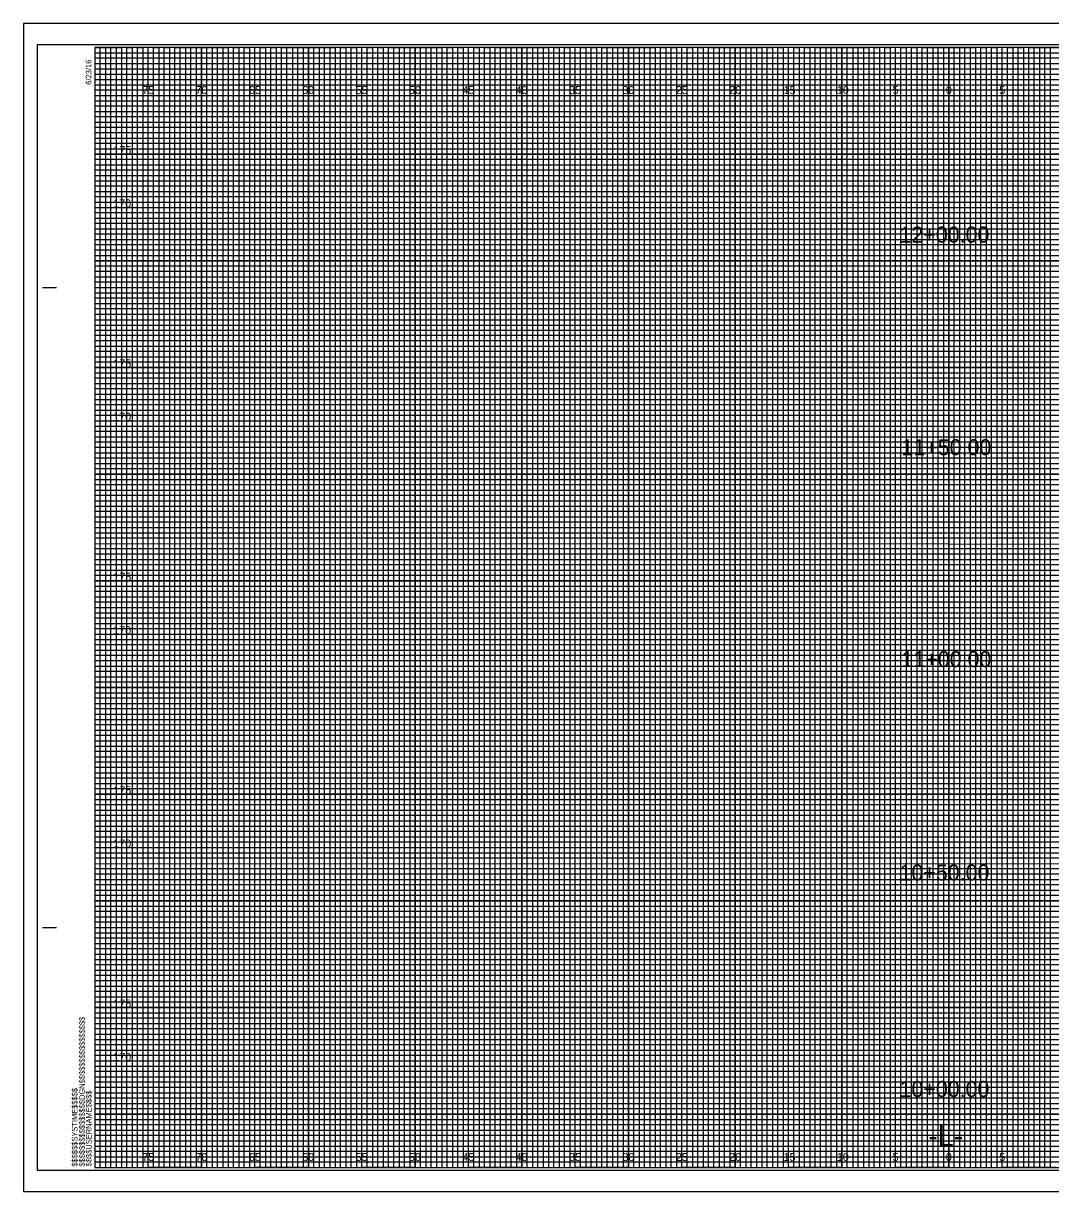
# Model space of a CAD drawing. Extents: x -7 to 186, y -2 to 107.
# Drawn here: x -6.7 to 89.5, y -2.3 to 107.3 of the extents above; entities that cross this region are included whole.
import ezdxf

# ---------------------------------------------------------------- set-up
doc = ezdxf.new("R2010")
doc.units = 0
for name, color, linetype in [('Prop XS Alignment Label', 7, 'Continuous'), ('Prop XS Elevation Labels', 7, 'Continuous'), ('Prop XS Offset Labels', 7, 'Continuous'), ('Prop XS Station Labels', 7, 'Continuous'), ('Sheet Cross Section CELL', 7, 'Continuous'), ('Sheet Cross Section Grid Major CELL', 7, 'Continuous'), ('Sheet Cross Section Grid Middle CELL', 7, 'Continuous'), ('Sheet Cross Section Grid Minor 1 CELL', 7, 'Continuous'), ('Sheet Cross Section Grid Minor 2 CELL', 7, 'Continuous'), ('Sheet Cutting Line CELL', 7, 'Continuous'), ('Sheet DOT Grid CELL', 7, 'Continuous'), ('Sheet Plot Border Inside CELL', 7, 'Continuous'), ('Sheet Plot Border Outside CELL', 7, 'Continuous')]:
    doc.layers.add(name, color=color, linetype=linetype)

msp = doc.modelspace()

# ---------------------------------------------------------------- linework, layer by layer
at = {"layer": 'Sheet Cross Section CELL'}
for p, q in [((-4.9, 82.5), (-3.65, 82.5)), ((-4.85, 82.5), (-3.6, 82.5)), ((-4.9, 22.5), (-3.65, 22.5)), ((-4.85, 22.5), (-3.6, 22.5)), ((0, 0), (0, 0)), ((0, 0), (0, 0)), ((0, 0), (0, 0)), ((0, 0), (0, 0)), ((0, 0), (0, 0)), ((0, 0), (0, 0)), ((0, 0), (0, 0))]:
    msp.add_line(p, q, dxfattribs=at)
msp.add_lwpolyline([(160, 105), (0, 105), (0, 0), (160, 0)], close=True, dxfattribs=at)
at = {"layer": 'Sheet Cross Section Grid Major CELL'}
for p, q in [((5, 105), (0, 105)), ((5, 0), (5, 105)), ((15, 105), (10, 105)), ((10, 105), (10, 0)), ((15, 0), (15, 105)), ((25, 105), (20, 105)), ((20, 105), (20, 0)), ((25, 0), (25, 105)), ((35, 105), (30, 105)), ((30, 105), (30, 0)), ((35, 0), (35, 105)), ((45, 105), (40, 105)), ((40, 105), (40, 0)), ((45, 0), (45, 105)), ((55, 105), (50, 105)), ((50, 105), (50, 0)), ((55, 0), (55, 105)), ((65, 105), (60, 105)), ((60, 105), (60, 0)), ((65, 0), (65, 105)), ((75, 105), (70, 105)), ((70, 105), (70, 0)), ((75, 0), (75, 105)), ((85, 105), (80, 105)), ((80, 105), (80, 0)), ((85, 0), (85, 105)), ((10, 0), (5, 0)), ((20, 0), (15, 0)), ((30, 0), (25, 0)), ((40, 0), (35, 0)), ((50, 0), (45, 0)), ((60, 0), (55, 0)), ((70, 0), (65, 0)), ((80, 0), (75, 0)), ((90, 0), (85, 0))]:
    msp.add_line(p, q, dxfattribs=at)
for points in [[(0, 100), (160, 100), (160, 95), (0, 95)], [(0, 90), (160, 90), (160, 85), (0, 85)], [(0, 80), (160, 80), (160, 75), (0, 75)], [(0, 70), (160, 70), (160, 65), (0, 65)], [(0, 60), (160, 60), (160, 55), (0, 55)], [(0, 50), (160, 50), (160, 45), (0, 45)], [(0, 40), (160, 40), (160, 35), (0, 35)], [(0, 30), (160, 30), (160, 25), (0, 25)], [(0, 20), (160, 20), (160, 15), (0, 15)], [(0, 10), (160, 10), (160, 5), (0, 5)]]:
    msp.add_lwpolyline(points, dxfattribs=at)
at = {"layer": 'Sheet Cross Section Grid Middle CELL'}
for points in [[(0, 105), (2.5, 105), (2.5, 0), (7.5, 0), (7.5, 105), (12.5, 105), (12.5, 0), (17.5, 0), (17.5, 105), (22.5, 105), (22.5, 0), (27.5, 0), (27.5, 105), (32.5, 105), (32.5, 0), (37.5, 0), (37.5, 105), (42.5, 105), (42.5, 0), (47.5, 0), (47.5, 105), (52.5, 105), (52.5, 0), (57.5, 0), (57.5, 105), (62.5, 105), (62.5, 0), (67.5, 0), (67.5, 105), (72.5, 105), (72.5, 0), (77.5, 0), (77.5, 105), (82.5, 105), (82.5, 0), (87.5, 0), (87.5, 105), (92.5, 105)], [(0, 102.5), (137.5, 102.5)], [(0, 92.5), (160, 92.5), (160, 97.5), (0, 97.5)], [(0, 82.5), (160, 82.5), (160, 87.5), (0, 87.5)], [(0, 72.5), (160, 72.5), (160, 77.5), (0, 77.5)], [(0, 62.5), (160, 62.5), (160, 67.5), (0, 67.5)], [(0, 52.5), (160, 52.5), (160, 57.5), (0, 57.5)], [(0, 42.5), (160, 42.5), (160, 47.5), (0, 47.5)], [(0, 32.5), (160, 32.5), (160, 37.5), (0, 37.5)], [(0, 22.5), (160, 22.5), (160, 27.5), (0, 27.5)], [(0, 12.5), (160, 12.5), (160, 17.5), (0, 17.5)], [(0, 2.5), (160, 2.5), (160, 7.5), (0, 7.5)]]:
    msp.add_lwpolyline(points, dxfattribs=at)
at = {"layer": 'Sheet Cross Section Grid Minor 1 CELL'}
for p, q in [((0, 104.5), (130, 104.5)), ((130, 103.99), (0, 103.99)), ((0, 103.99), (0, 103.5)), ((0, 103.5), (130, 103.5)), ((130, 102.95), (0, 102.95)), ((0, 102.95), (0, 102)), ((0, 102), (160, 102))]:
    msp.add_line(p, q, dxfattribs=at)
for points in [[(0, 101.5), (135, 101.5), (160, 101.5), (160, 101), (0, 101)], [(0, 100.5), (160, 100.5), (160, 99.5), (0, 99.5)], [(0, 99), (160, 99), (160, 98.5), (0, 98.49)], [(0, 98), (160, 98), (160, 97), (0, 97)], [(0, 96.5), (160, 96.5), (160, 96), (0, 96)], [(0, 95.5), (160, 95.5), (160, 94.5), (0, 94.5)], [(0, 94), (160, 94), (160, 93.5), (0, 93.5)], [(0, 93), (160, 93), (160, 92), (0, 92)], [(0, 91.5), (160, 91.5), (160, 91), (0, 91)], [(0, 90.5), (160, 90.5), (160, 89.5), (0, 89.5)], [(0, 89), (160, 89), (160, 88.5), (0, 88.5)], [(0, 88), (160, 88), (160, 86.98), (160, 86.5), (160, 86), (0, 86)], [(0, 87), (160, 87), (160, 86.5), (0, 86.5)], [(0, 85.5), (160, 85.5), (160, 84.5), (0, 84.52)], [(0, 84.52), (160, 84.5), (160, 84), (0, 84)], [(0, 83.5), (160, 83.5), (160, 83), (0, 83)], [(0, 82), (160, 82), (160, 81.5), (0, 81.5)], [(0, 81), (160, 81), (160, 80.5), (0, 80.5)], [(-0.04, 79.45), (160, 79.45), (160, 78.94), (-0.04, 78.94)], [(0, 78.5), (160, 78.5), (160, 78), (0, 78)], [(0, 77), (160, 77), (160, 76.5), (0, 76.5)], [(0, 76), (160, 76), (160, 75.5), (0, 75.5)], [(0, 74.5), (160, 74.5), (160, 74), (0, 74)], [(0, 73.5), (160, 73.5), (160, 73), (0, 73)], [(0, 72), (160, 72), (160, 71.5), (0, 71.5)], [(0, 71), (160, 71), (160, 70.5), (0, 70.5)], [(0, 69.5), (160, 69.5), (160, 68.99), (0, 69)], [(0, 68.5), (160, 68.5), (160, 68), (0, 68)], [(0, 67), (160, 67), (160, 66.5), (0, 66.5)], [(0, 66), (160, 66), (160, 65.5), (0, 65.5)], [(0, 64.5), (160, 64.5), (160, 64), (0, 64)], [(0, 63.5), (160, 63.5), (160, 63), (0, 63)], [(0, 62), (160, 62), (160, 61.5), (0, 61.5)], [(0, 61), (160, 61), (160, 60.5), (0, 60.5)], [(0, 59.5), (160, 59.5), (160, 59), (0, 59)], [(0, 58.5), (160.03, 58.45), (160, 58), (0, 58)], [(0, 57), (160, 57), (160, 56.5), (0, 56.5)], [(0, 56), (160, 56), (160, 55.5), (0, 55.5)], [(0, 54.5), (160, 54.5), (160, 54), (0, 54)], [(0, 53.5), (160, 53.5), (160, 53), (0, 53)], [(0, 52), (160, 52), (160, 51.5), (0, 51.5)], [(0, 51), (160, 51), (160, 50.5), (0, 50.5)], [(0, 49.5), (160, 49.5), (160, 49), (0, 49)], [(0, 48.5), (160, 48.5), (160, 48), (0, 48)], [(0, 47), (160, 47), (160, 46.5), (0, 46.5)], [(0, 46), (160, 46), (160, 45.5), (0, 45.5)], [(0, 44.5), (160, 44.5), (160, 44), (0, 44)], [(0, 43.5), (160, 43.5), (160, 43), (0, 43)], [(0, 42), (160, 42), (160, 41.5), (0, 41.5)], [(0, 41), (160, 41), (160, 40.5), (0, 40.5)], [(0, 39.5), (160, 39.5), (160, 38.99), (0, 39)], [(0, 38.5), (160, 38.5), (160, 38), (0, 38)], [(0, 37), (160, 37), (160, 36.5), (0, 36.5)], [(0, 36), (160, 36), (160, 35.5), (0, 35.5)], [(0, 34.5), (160, 34.5), (160, 34), (0, 34)], [(0, 33.5), (160, 33.5), (160, 33), (0, 33)], [(0, 32), (160, 32), (160, 31.5), (0, 31.5)], [(0, 31), (160, 31), (160, 30.5), (0, 30.5)], [(0, 29.5), (160, 29.5), (160, 29), (0, 29)], [(0, 28.5), (160.03, 28.46), (160, 28), (0, 28)], [(0, 27), (160, 27), (160, 26.5), (0, 26.5)], [(0, 26), (160, 26), (160, 25.5), (0, 25.5)], [(0, 24.5), (160, 24.5), (160, 24), (0, 24)], [(0, 23.5), (160, 23.5), (160, 23), (0, 23)], [(0, 22), (160, 22), (160, 21.5), (0, 21.5)], [(0, 21), (160, 21), (160, 20.5), (0, 20.5)], [(0, 19.5), (160, 19.5), (160, 19), (0, 19)], [(0, 18.5), (160, 18.5), (160, 18), (0, 18)], [(0, 17), (160, 17), (160, 16.5), (0, 16.5)], [(0, 16), (160, 16), (160, 15.5), (0, 15.5)], [(0, 14.5), (160, 14.5), (160, 14), (0, 14)], [(0, 13.5), (160, 13.5), (160, 13), (0, 13)], [(0, 12), (160, 12), (160, 11.5), (0, 11.5)], [(0, 11), (160, 11), (160, 10.5), (0, 10.5)], [(0, 9.5), (160, 9.5), (160, 9), (0, 9)], [(0, 8.5), (160, 8.5), (160, 8), (0, 8)], [(0, 7), (160, 7), (160, 6.5), (0, 6.5)], [(0, 6), (160, 6), (160, 5.5), (0, 5.5)], [(0, 4.5), (160, 4.5), (160, 4), (0, 4)], [(0, 3.5), (160, 3.5), (160, 3), (0, 3)], [(0, 2), (160, 2), (160, 1.5), (0, 1.5)], [(0, 1), (160, 1), (160, 0.5), (0, 0.5)]]:
    msp.add_lwpolyline(points, dxfattribs=at)
at = {"layer": 'Sheet Cross Section Grid Minor 2 CELL'}
for points in [[(0, 0), (0.5, 0), (0.5, 105), (1, 105), (1, 0)], [(1, 0), (1.5, 0), (1.5, 105), (2, 105), (2, 0)], [(2.5, 0), (3, 0), (3, 105), (3.5, 105), (3.5, 0)], [(3.5, 0), (4, 0), (4, 105), (4.5, 105), (4.5, 0)], [(5, 0), (5.5, 0), (5.5, 105), (6, 105), (6, 0)], [(6, 0), (6.5, 0), (6.5, 105), (7, 105), (7, 0)], [(7.5, 0), (8, 0), (8, 105), (8.5, 105), (8.5, 0)], [(8.5, 0), (9, 0), (9, 105), (9.5, 105), (9.5, 0)], [(10, 0), (10.5, 0), (10.5, 105), (11, 105), (11, 0)], [(11, 0), (11.5, 0), (11.5, 105), (12, 105), (12, 0)], [(12.5, 0), (13, 0), (13, 105), (13.5, 105), (13.5, 0)], [(13.5, 0), (14, 0), (14, 105), (14.5, 105), (14.5, 0)], [(15, 0), (15.5, 0), (15.5, 105), (16, 105), (16, 0)], [(16, 0), (16.5, 0), (16.5, 105), (17, 105), (17, 0)], [(17.5, 0), (18, 0), (18, 105), (18.5, 105), (18.5, 0)], [(18.5, 0), (19, 0), (19, 105), (19.5, 105), (19.5, 0)], [(20, 0), (20.5, 0), (20.5, 105), (21, 105), (21, 0)], [(21, 0), (21.5, 0), (21.5, 105), (22, 105), (22, 0)], [(22.5, 0), (23, 0), (23, 105), (23.5, 105), (23.5, 0)], [(23.5, 0), (24, 0), (24, 105), (24.5, 105), (24.5, 0)], [(25, 0), (25.5, 0), (25.5, 105), (26, 105), (26, 0)], [(26, 0), (26.5, 0), (26.5, 105), (27, 105), (27, 0)], [(27.5, 0), (28, 0), (28, 105), (28.5, 105), (28.5, 0)], [(28.5, 0), (29, 0), (29, 105), (29.5, 105), (29.5, 0)], [(30, 0), (30.5, 0), (30.5, 105), (31, 105), (31, 0)], [(31, 0), (31.5, 0), (31.5, 105), (32, 105), (32, 0)], [(32.5, 0), (33, 0), (33, 105), (33.5, 105), (33.5, 0)], [(33.5, 0), (34, 0), (34, 105), (34.5, 105), (34.5, 0)], [(35, 0), (35.5, 0), (35.5, 105), (36, 105), (36, 0)], [(36, 0), (36.5, 0), (36.5, 105), (37, 105), (37, 0)], [(37.5, 0), (38, 0), (38, 105), (38.5, 105), (38.5, 0)], [(38.5, 0), (39, 0), (39, 105), (39.5, 105), (39.5, 0)], [(40, 0), (40.5, 0), (40.5, 105), (41, 105), (41, 0)], [(41, 0), (41.5, 0), (41.5, 105), (42, 105), (42, 0)], [(42.5, 0), (43, 0), (43, 105), (43.5, 105), (43.5, 0)], [(43.5, 0), (44, 0), (44, 105), (44.5, 105), (44.5, 0)], [(45, 0), (45.5, 0), (45.5, 105), (46, 105), (46, 0)], [(46, 0), (46.5, 0), (46.5, 105), (47, 105), (47, 0)], [(47.5, 0), (48, 0), (48, 105), (48.5, 105), (48.5, 0)], [(48.5, 0), (49, 0), (49, 105), (49.5, 105), (49.5, 0)], [(50, 0), (50.5, 0), (50.5, 105), (51, 105), (51, 0)], [(51, 0), (51.5, 0), (51.5, 105), (52, 105), (52, 0)], [(52.5, 0), (53, 0), (53, 105), (53.5, 105), (53.5, 0)], [(53.5, 0), (54, 0), (54, 105), (54.5, 105), (54.5, 0)], [(55, 0), (55.5, 0), (55.5, 105), (56, 105), (56, 0)], [(56, 0), (56.5, 0), (56.5, 105), (57, 105), (57, 0)], [(57.5, 0), (58, 0), (58, 105), (58.5, 105), (58.5, 0)], [(58.5, 0), (59, 0), (59, 105), (59.5, 105), (59.5, 0)], [(60, 0), (60.5, 0), (60.5, 105), (61, 105), (61, 0)], [(61, 0), (61.5, 0), (61.5, 105), (62, 105), (62, 0)], [(62.5, 0), (63, 0), (63, 105), (63.5, 105), (63.5, 0)], [(63.5, 0), (64, 0), (64, 105), (64.5, 105), (64.5, 0)], [(65, 0), (65.5, 0), (65.5, 105), (66, 105), (66, 0)], [(66, 0), (66.5, 0), (66.5, 105), (67, 105), (67, 0)], [(67.5, 0), (68, 0), (68, 105), (68.5, 105), (68.5, 0)], [(68.5, 0), (69, 0), (69, 105), (69.5, 105), (69.5, 0)], [(70, 0), (70.5, 0), (70.5, 105), (71, 105), (71, 0)], [(71, 0), (71.5, 0), (71.5, 105), (72, 105), (72, 0)], [(72.5, 0), (73, 0), (73, 105), (73.5, 105), (73.5, 0)], [(73.5, 0), (74, 0), (74, 105), (74.5, 105), (74.5, 0)], [(75, 0), (75.5, 0), (75.5, 105), (76, 105), (76, 0)], [(76, 0), (76.5, 0), (76.5, 105), (77, 105), (77, 0)], [(77.5, 0), (78, 0), (78, 105), (78.5, 105), (78.5, 0)], [(78.5, 0), (79, 0), (79, 105), (79.5, 105), (79.5, 0)], [(80, 0), (80.5, 0), (80.5, 105), (81, 105), (81, 0)], [(81, 0), (81.5, 0), (81.5, 105), (82, 105), (82, 0)], [(82.5, 0), (83, 0), (83, 105), (83.5, 105), (83.5, 0)], [(83.5, 0), (84, 0), (84, 105), (84.5, 105), (84.5, 0)], [(85, 0), (85.5, 0), (85.5, 105), (86, 105), (86, 0)], [(86, 0), (86.5, 0), (86.5, 105), (87, 105), (87, 0)], [(87.5, 0), (88, 0), (88, 105), (88.5, 105), (88.5, 0)], [(88.5, 0), (89, 0), (89, 105), (89.5, 105), (89.5, 0)]]:
    msp.add_lwpolyline(points, dxfattribs=at)
at = {"layer": 'Sheet Cutting Line CELL'}
for p, q in [((161.65, 107.25), (-6.7, 107.25)), ((-6.7, 107.25), (-6.7, -2.25)), ((-6.7, -2.25), (161.65, -2.25))]:
    msp.add_line(p, q, dxfattribs=at)
at = {"layer": 'Sheet DOT Grid CELL'}
for p, q in [((5, 0), (5, 105)), ((10, 0), (10, 105)), ((15, 0), (15, 105)), ((20, 0), (20, 105)), ((25, 0), (25, 105)), ((30, 0), (30, 105)), ((35, 0), (35, 105)), ((40, 0), (40, 105)), ((45, 0), (45, 105)), ((50, 0), (50, 105)), ((55, 0), (55, 105)), ((60, 0), (60, 105)), ((65, 0), (65, 105)), ((70, 0), (70, 105)), ((75, 0), (75, 105)), ((80, 0), (80, 105)), ((85, 0), (85, 105)), ((0, 100), (160, 100)), ((0, 95), (160, 95)), ((0, 90), (160, 90)), ((0, 85), (160, 85)), ((0, 80), (160, 80)), ((0, 75), (160, 75)), ((0, 70), (160, 70)), ((0, 65), (160, 65)), ((0, 60), (160, 60)), ((0, 55), (160, 55)), ((0, 50), (160, 50)), ((0, 45), (160, 45)), ((0, 40), (160, 40)), ((0, 35), (160, 35)), ((0, 30), (160, 30)), ((0, 25), (160, 25)), ((0, 20), (160, 20)), ((0, 15), (160, 15)), ((0, 10), (160, 10)), ((0, 5), (160, 5))]:
    msp.add_line(p, q, dxfattribs=at)
at = {"layer": 'Sheet Plot Border Inside CELL'}
msp.add_lwpolyline([(-5.4, -0.25), (161.2, -0.25), (161.2, 105.25), (-5.4, 105.25)], close=True, dxfattribs=at)
at = {"layer": 'Sheet Plot Border Outside CELL'}
msp.add_lwpolyline([(-6.7, -2.25), (161.65, -2.25), (161.65, 107.25), (-6.7, 107.25)], close=True, dxfattribs=at)

# ---------------------------------------------------------------- texts
at = {"layer": 'Prop XS Alignment Label'}
msp.add_text('-L-', height=2, dxfattribs=at).set_placement((78.08, 2))
at = {"layer": 'Prop XS Elevation Labels'}
for s, p in [('175', (1.73, 95)), ('170', (1.72, 90)), ('175', (1.73, 75)), ('170', (1.72, 70)), ('175', (1.73, 55)), ('170', (1.72, 50)), ('175', (1.73, 35)), ('170', (1.72, 30)), ('175', (1.73, 15)), ('170', (1.72, 10))]:
    msp.add_text(s, height=0.75, dxfattribs=at).set_placement(p)
at = {"layer": 'Prop XS Offset Labels'}
for s, p in [('75', (4.44, 100.62)), ('70', (9.43, 100.62)), ('65', (14.44, 100.62)), ('60', (19.43, 100.62)), ('55', (24.44, 100.62)), ('50', (29.43, 100.62)), ('45', (34.44, 100.62)), ('40', (39.43, 100.62)), ('35', (44.44, 100.62)), ('30', (49.43, 100.62)), ('25', (54.44, 100.62)), ('20', (59.43, 100.62)), ('15', (64.53, 100.62)), ('10', (69.52, 100.62)), ('5', (74.74, 100.62)), ('0', (79.73, 100.62)), ('0', (79.73, 100.62)), ('5', (84.74, 100.62)), ('75', (4.44, 0.62)), ('70', (9.43, 0.62)), ('65', (14.44, 0.62)), ('60', (19.43, 0.62)), ('55', (24.44, 0.62)), ('50', (29.43, 0.62)), ('45', (34.44, 0.62)), ('40', (39.43, 0.62)), ('35', (44.44, 0.62)), ('30', (49.43, 0.62)), ('25', (54.44, 0.62)), ('20', (59.43, 0.62)), ('15', (64.53, 0.62)), ('10', (69.52, 0.62)), ('5', (74.74, 0.62)), ('0', (79.73, 0.62)), ('0', (79.73, 0.62)), ('5', (84.74, 0.62))]:
    msp.add_text(s, height=0.75, dxfattribs=at).set_placement(p)
at = {"layer": 'Prop XS Station Labels'}
for s, p in [('12+00.00', (75.39, 86.7)), ('11+50.00', (75.57, 66.77)), ('11+00.00', (75.57, 46.91)), ('10+50.00', (75.39, 26.91)), ('10+00.00', (75.39, 6.62))]:
    msp.add_text(s, height=1.5, dxfattribs=at).set_placement(p)
at = {"layer": 'Sheet Cross Section CELL'}
for s, p in [('6/23/16', (-0.33, 101.5)), ('$$$$$$$$$$$$$$$$DGN$$$$$$$$$$$$$$$$', (-0.94, 0.09)), ('$$$$$$SYSTIME$$$$$', (-1.63, 0.09)), ('$$$$USERNAME$$$$', (-0.31, 0.12))]:
    msp.add_text(s, height=0.525, rotation=90, dxfattribs=at).set_placement(p)

doc.saveas('drawing.dxf')
